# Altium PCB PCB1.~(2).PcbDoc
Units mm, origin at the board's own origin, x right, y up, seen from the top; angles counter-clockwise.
Board outline 70 x 70 mm, 4 copper layers (Top Layer, Internal Plane 1, Internal Plane 2, Bottom Layer), stack 0.462 mm thick; 10 components, 13 nets, 53 pads, 0 vias.
Unrouted connection lines stored in the file: 38.
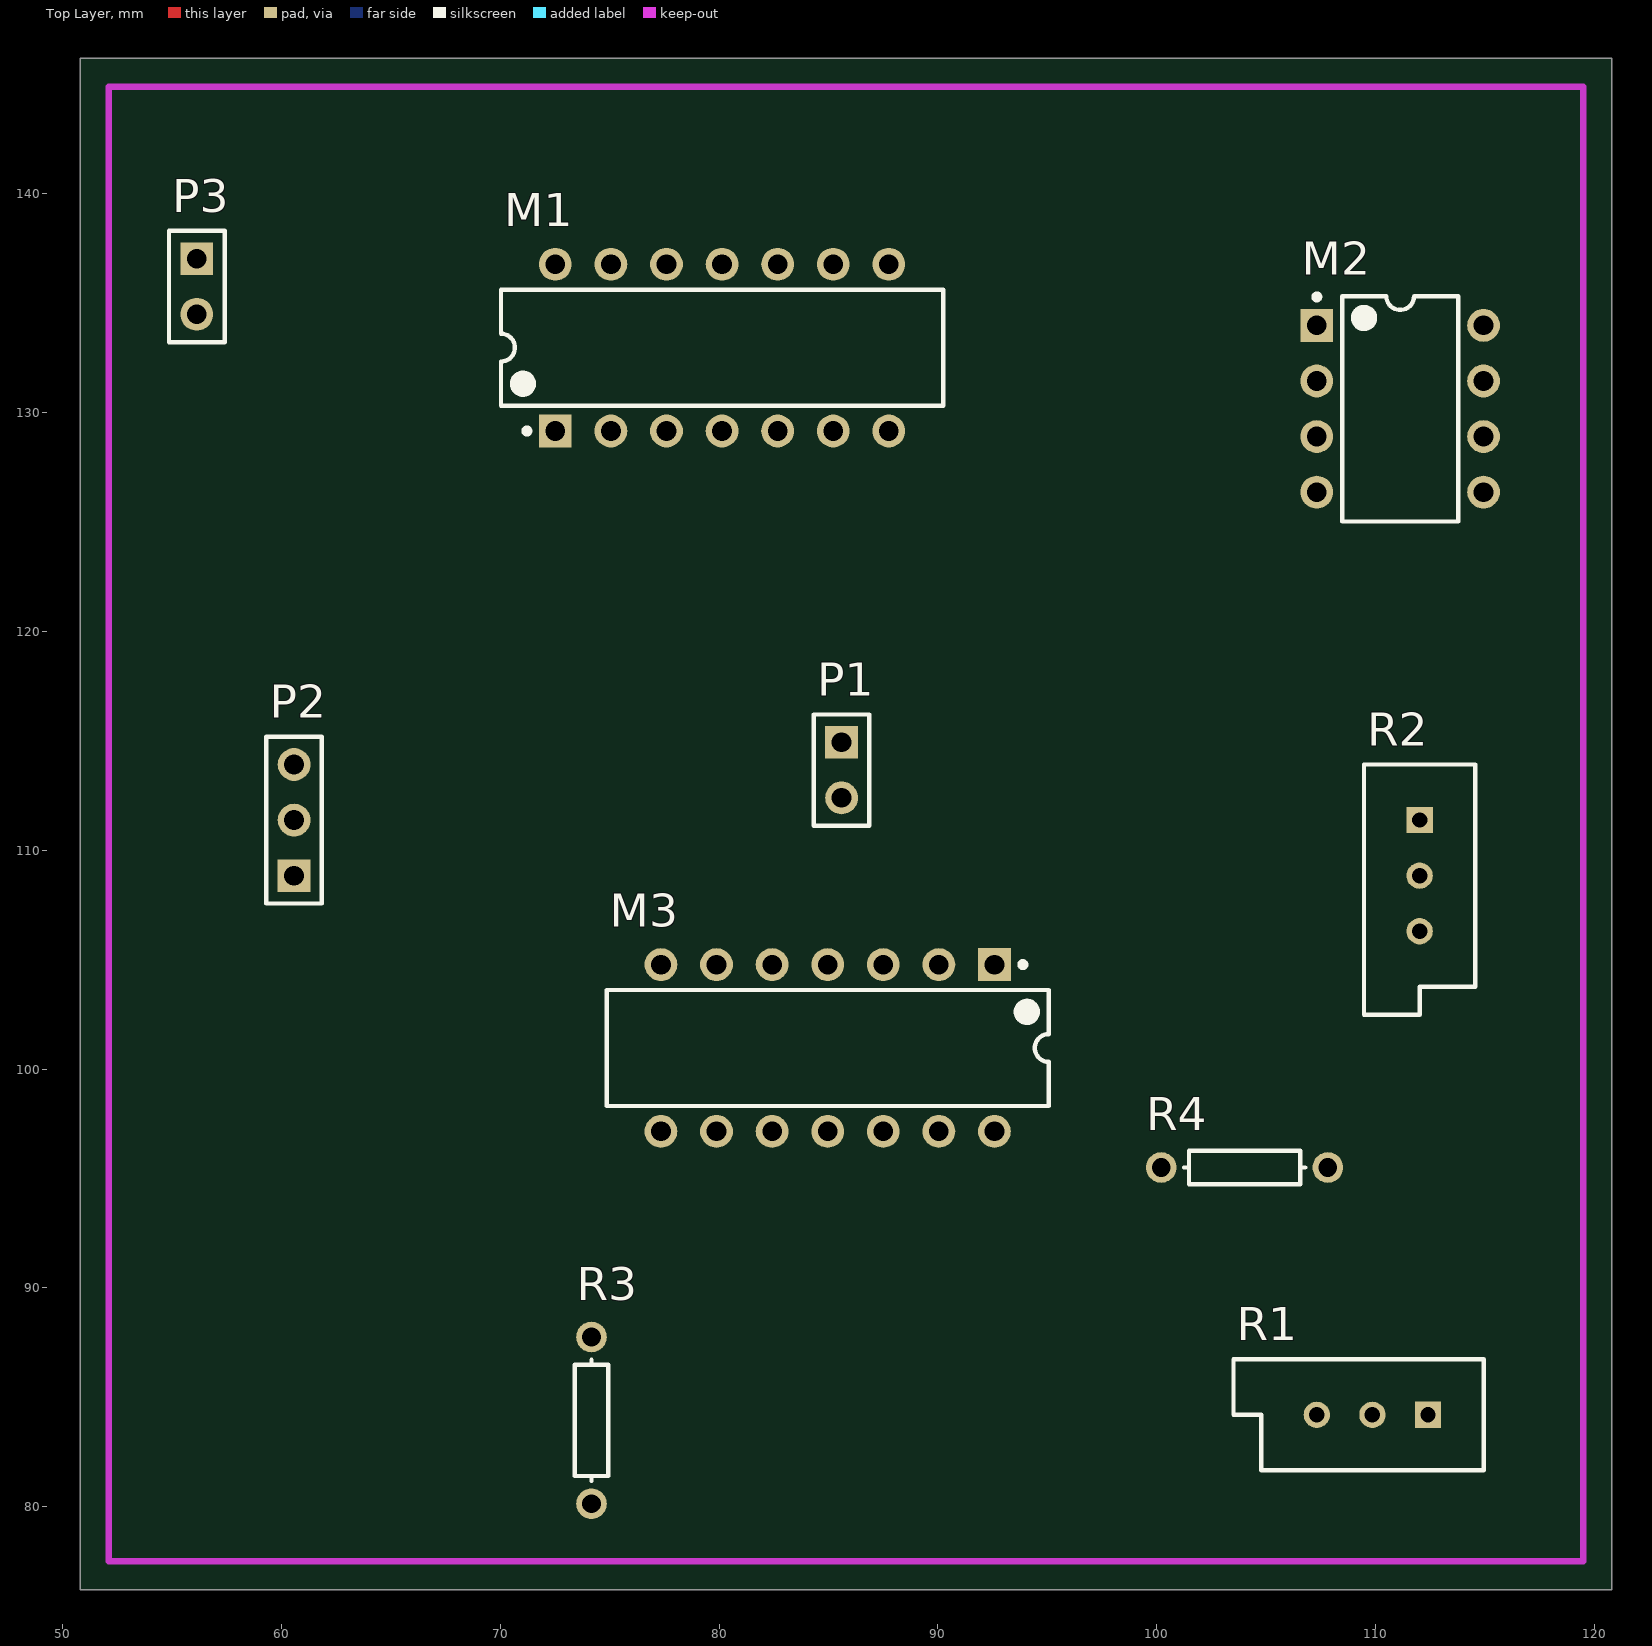
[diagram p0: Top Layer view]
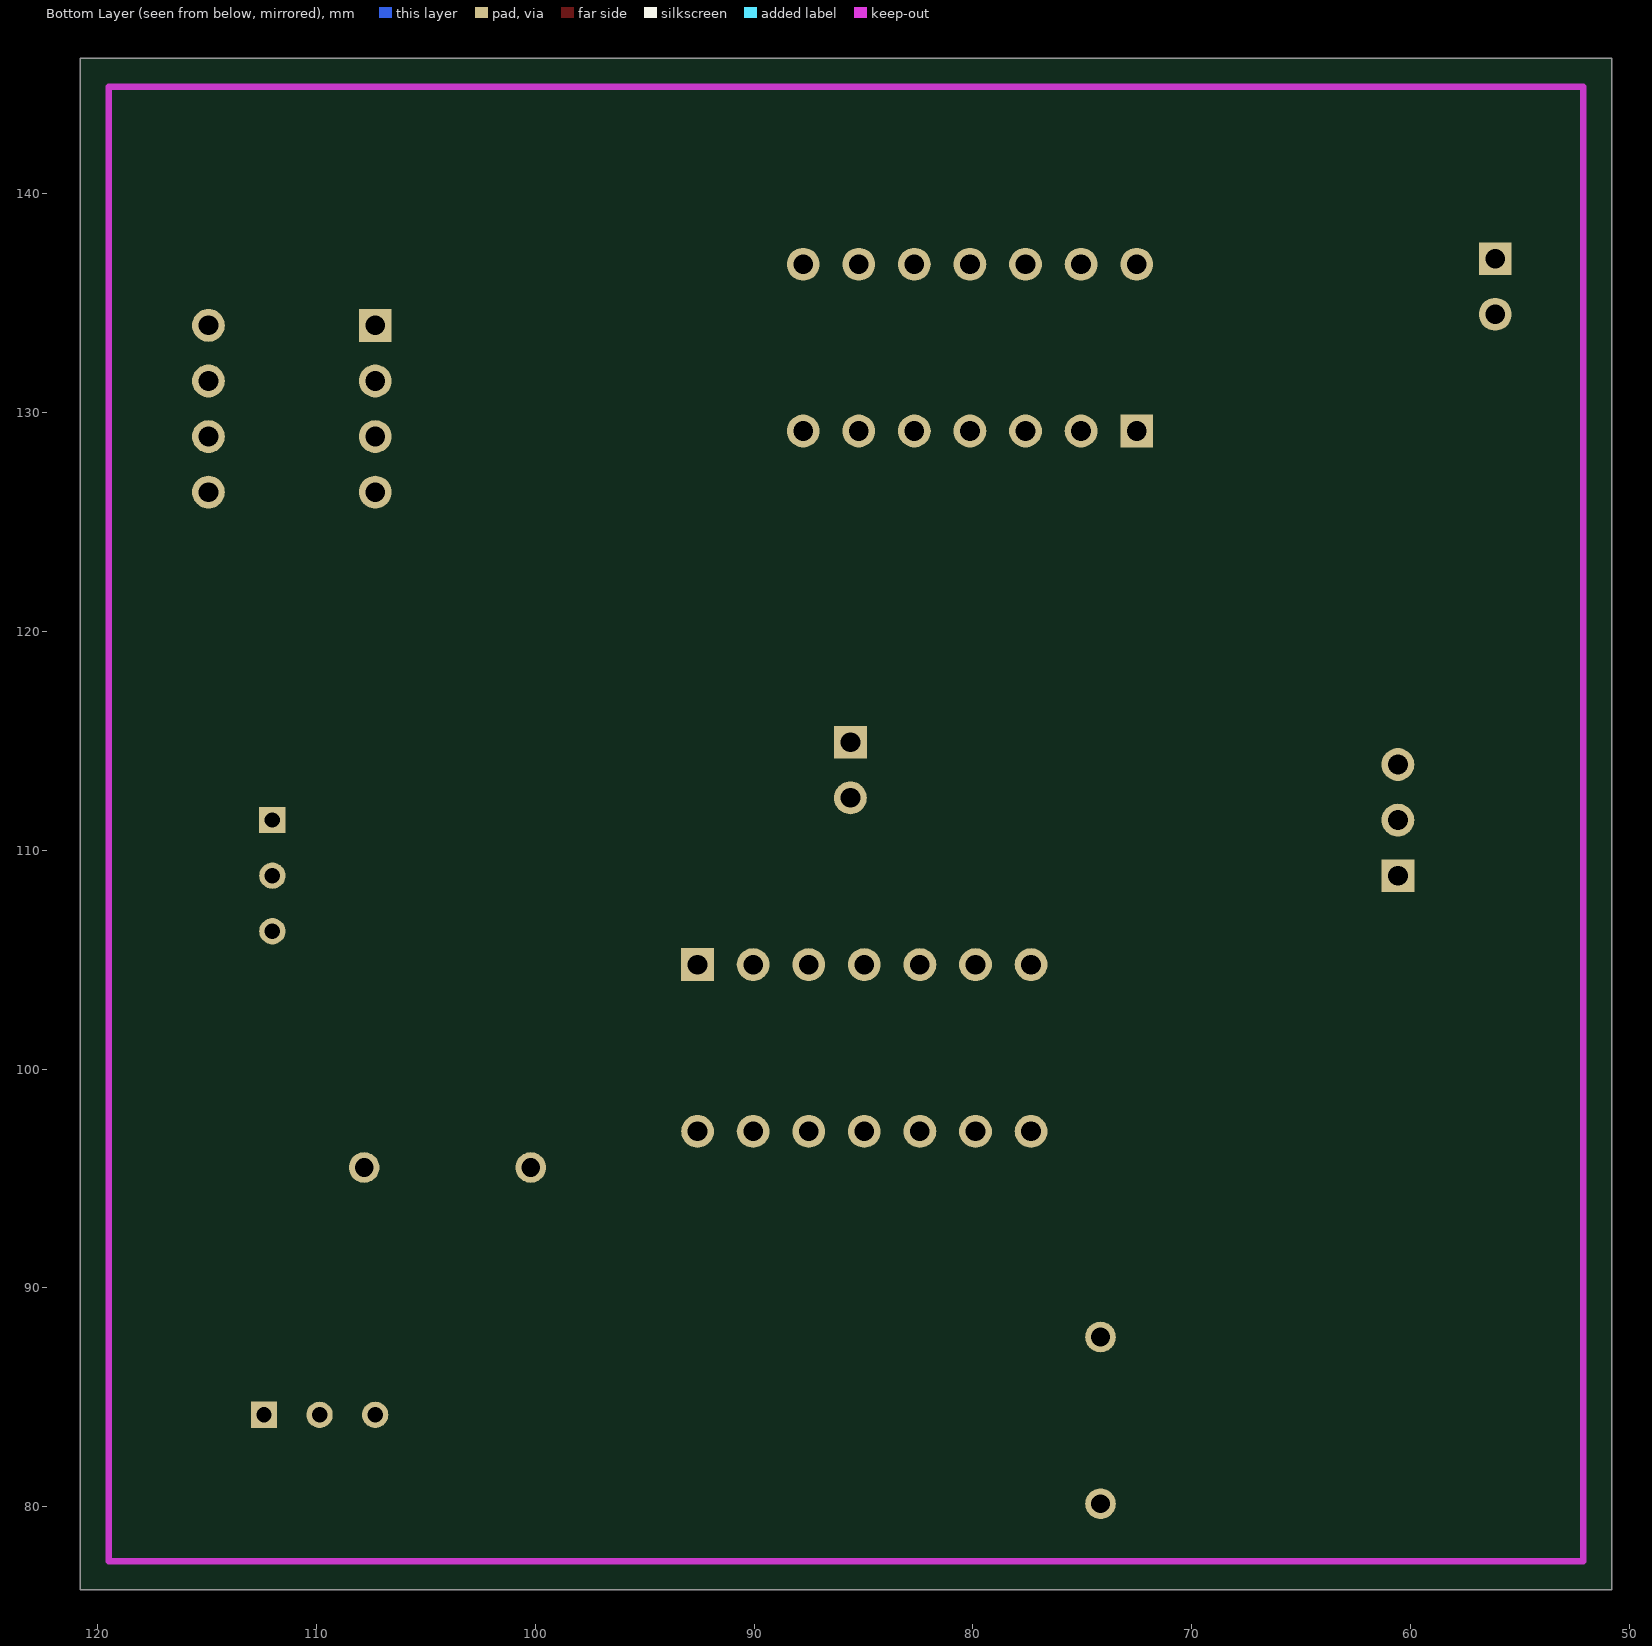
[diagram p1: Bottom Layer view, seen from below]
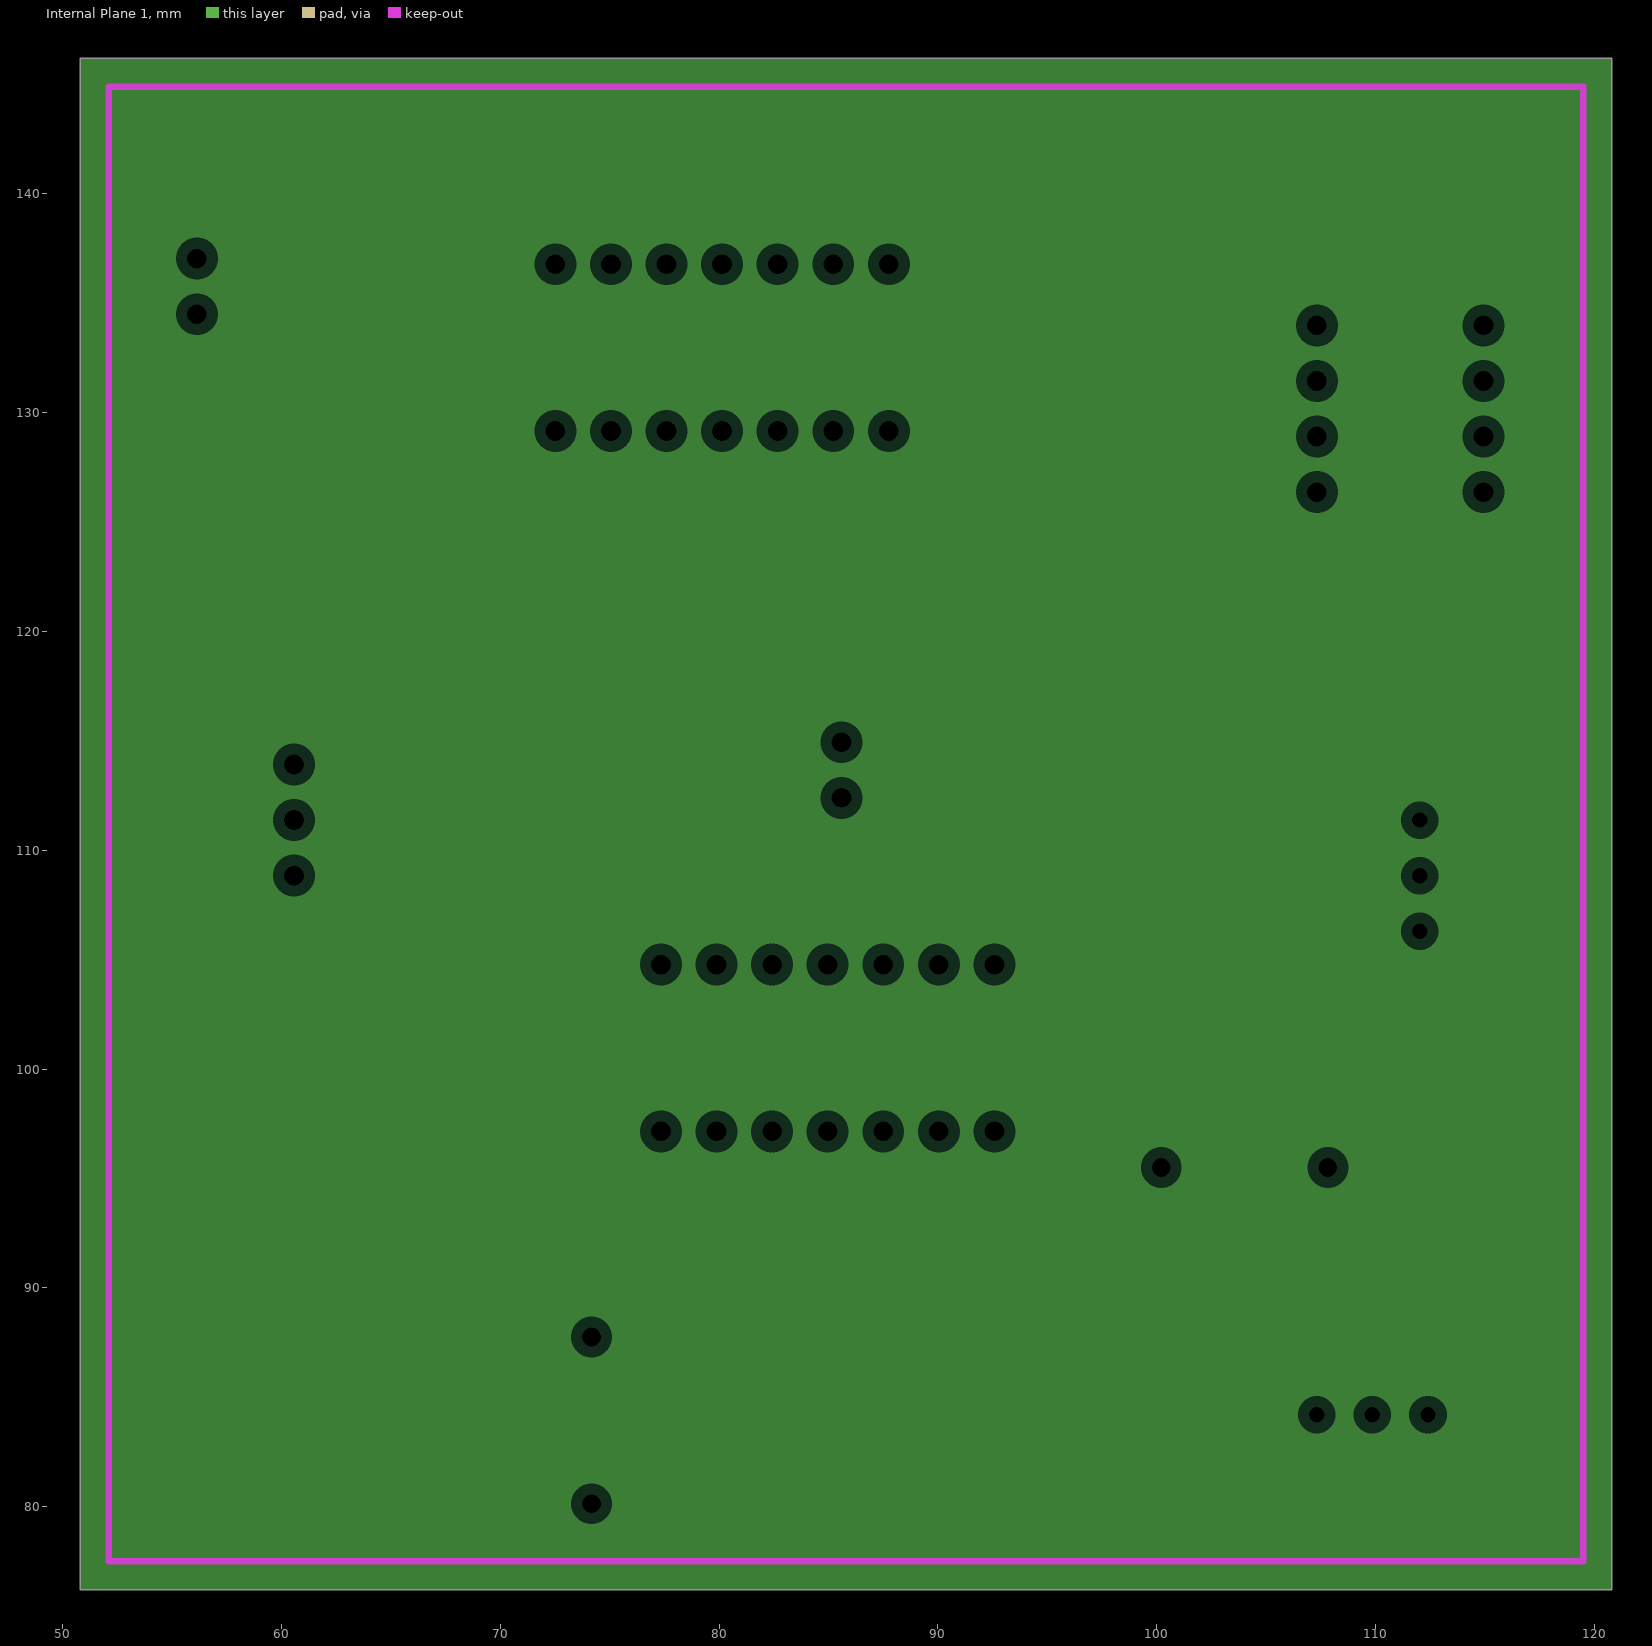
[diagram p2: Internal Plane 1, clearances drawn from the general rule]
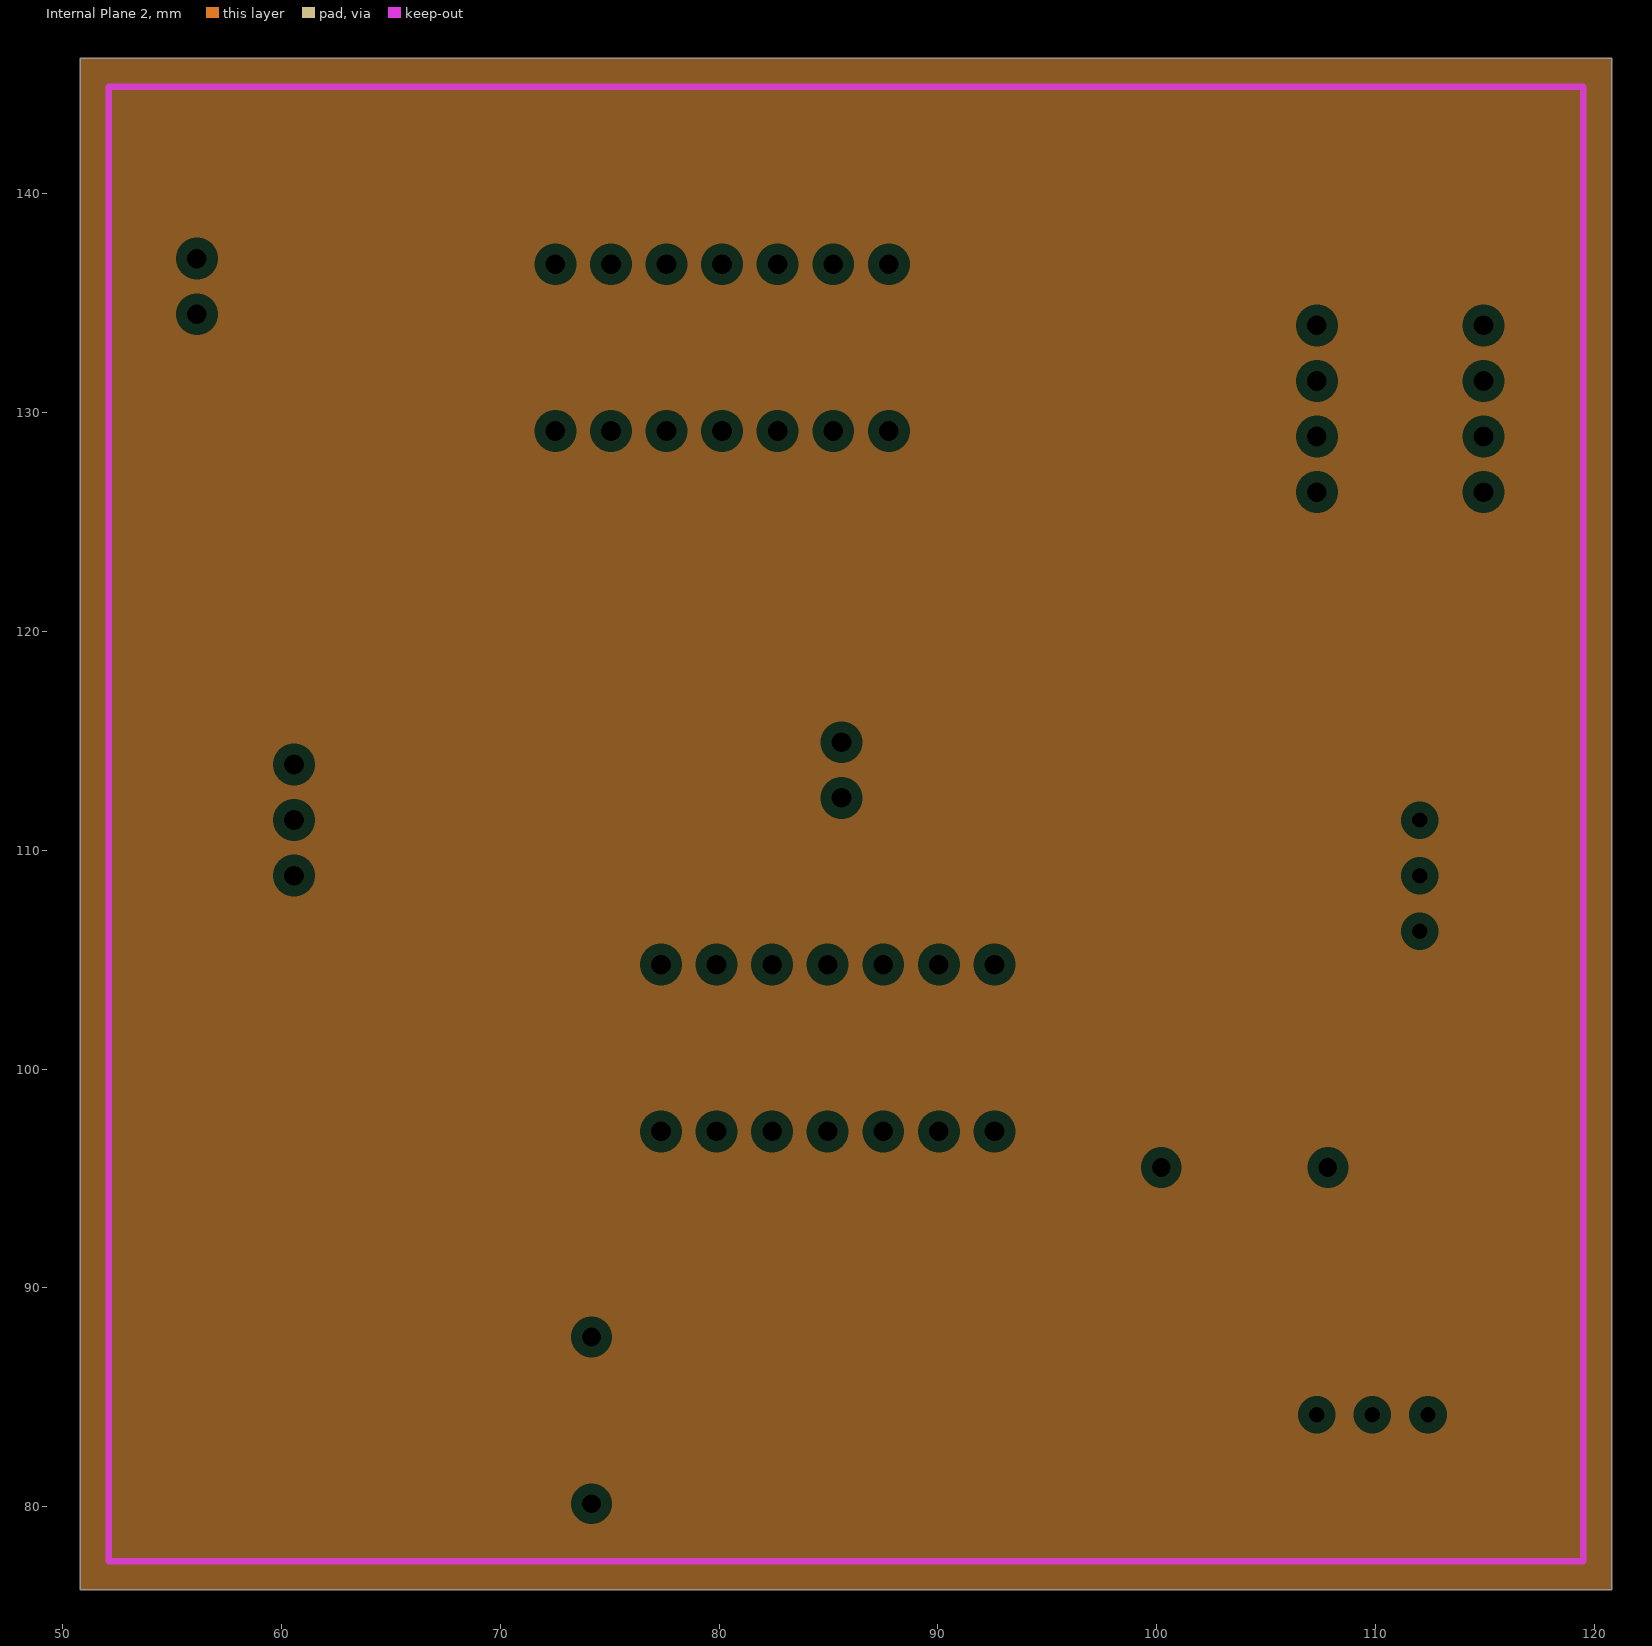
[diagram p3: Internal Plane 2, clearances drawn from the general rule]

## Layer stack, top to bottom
Top Solder: solder mask 0.0102, Solder Resist, Dk 3.5
Top Layer: signal copper 0.0356
Internal Plane 1: plane copper 0.0356
Internal Plane 2: plane copper 0.0356
Dielectric 1: dielectric 0.32, FR-4, Dk 4.8
Bottom Layer: signal copper 0.0356
Bottom Solder: solder mask 0.0102, Solder Resist, Dk 3.5

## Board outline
50.8,76.2 120.8,76.2 120.8,146.2 50.8,146.2

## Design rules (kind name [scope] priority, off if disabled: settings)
Clearance [All] p1: gap=0.8
PlaneClearance [All] p1: clearance=0.508
PlaneConnect [All] p1: planeconnectstyle=Relief reliefexpansion=0.508 reliefentries=4 reliefconductorwidth=0.254 reliefairgap=0.254
PolygonConnect [All] p1: connectstyle=Relief reliefconductorwidth=0.254 reliefentries=4 polygonreliefangle="90 Angle" airgapwidth=0.254
RoutingVias [All] p1: holewidth=0.8 width=1.6 viastyle="Through Hole" minholewidth=0.711 minwidth=1.27 maxholewidth=0.711 maxwidth=1.27
SolderMaskExpansion [All] p1: expansion=0.102
Width [All] p1: maxlimit=0.5 minlimit=0.5 preferedwidth=0.5
28 further rules are at their usual default settings.

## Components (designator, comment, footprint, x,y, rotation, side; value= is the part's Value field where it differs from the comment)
M1 "ALD1105" DIP-14 80.137,132.969 r90 top
M2 "ALD1117" DIP-8 111.125,130.175 r0 top
M3 "ALD1106" DIP-14 84.963,100.965 r270 top
P1 "Header 2" HDR1X2 85.598,114.935 r270 top
P2 "Header 3" HDR1X3 60.579,108.839 r90 top
P3 "Header 2" HDR1X2 56.134,137.033 r270 top
R1 "RPot" VR5 109.855,84.201 r180 top
R2 "RPot" VR5 112.014,108.839 r270 top
R3 "Res1" AXIAL-0.3 74.168,83.947 r90 top
R4 "Res1" AXIAL-0.3 104.013,95.504 r180 top

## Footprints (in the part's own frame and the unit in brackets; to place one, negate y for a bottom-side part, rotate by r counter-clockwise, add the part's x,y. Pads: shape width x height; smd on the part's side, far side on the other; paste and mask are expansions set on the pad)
AXIAL-0.3 [mm] "Axial Device, Thru-Hole; 2 Leads; 0.3 in Pin Spacing"
  round 1.4 hole 0.85: 1(-3.81,0) 2(3.81,0)
  silkscreen extent -2.77,-0.76 2.77,0.76
DIP-8 [mm] "DIP, 8-Pin, Row Spacing 7.62 mm, Pitch 2.54 mm"
  rect 1.5x1.5 hole 0.9: 1(-3.81,3.81)
  round 1.5 hole 0.9: 2(-3.81,1.27) 3(-3.81,-1.27) 4(-3.81,-3.81) 5(3.81,-3.81) 6(3.81,-1.27) 7(3.81,1.27) 8(3.81,3.81)
  silkscreen extent -3.93,-5.15 2.65,5.23, body extent -3.6,-5.15 3.6,5.15, height 5.33
DIP-14 [mm] "DIP, 14-Pin, Row Spacing 7.62 mm, Pitch 2.54 mm"
  rect 1.5x1.5 hole 0.9: 1(-3.81,7.62)
  round 1.5 hole 0.9: 2(-3.81,5.08) 3(-3.81,2.54) 4(-3.81,0) 5(-3.81,-2.54) 6(-3.81,-5.08) 7(-3.81,-7.62) 8(3.81,-7.62) 9(3.81,-5.08) 10(3.81,-2.54) 11(3.81,0) 12(3.81,2.54) 13(3.81,5.08) 14(3.81,7.62)
  silkscreen extent -3.93,-10.1 2.65,10.1, body extent -3.6,-10.1 3.6,10.1, height 5.08
HDR1X2 [mm] "Connector; Header; 2 Position"
  rect 1.5x1.5 hole 0.9: 1(0,0)
  round 1.5 hole 0.9: 2(2.54,0)
  silkscreen extent -1.27,-1.27 3.81,1.27
HDR1X3 [mm] "Connector; Header; 3 Position"
  rect 1.5x1.5 hole 0.9: 1(0,0)
  round 1.5 hole 0.9: 2(2.54,0) 3(5.08,0)
  silkscreen extent -1.27,-1.27 6.35,1.27
VR5 [mm] "Thru-Hole; 3 Leads"
  rect 1.2x1.2 hole 0.7: 1(-2.54,0)
  round 1.2 hole 0.7: 2(0,0) 3(2.54,0)
  silkscreen extent -5.08,-2.54 6.35,2.54

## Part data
M1: "Dual P-channel and dual N-channel matched MOSFET array"
M2: "Dual P-channel matched MOSFET array"
M3: "Quad N-channel matched MOSFET array"
P1 P3: "Header, 2-Pin"
P2: "Header, 3-Pin"
R1 R2: "Potentiometer"
R3 R4: "Resistor"

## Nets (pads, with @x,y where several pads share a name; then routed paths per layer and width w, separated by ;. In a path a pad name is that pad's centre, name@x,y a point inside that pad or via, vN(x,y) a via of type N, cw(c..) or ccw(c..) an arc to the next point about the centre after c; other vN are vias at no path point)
GND: P1.2 P2.3
IN+: M1.13 P3.1
IN-: M1.2 P3.2
NetM1_1: M1.1 M1.5 M1.6 M1.9
NetM1_3: M1.3 M1.4 M1.12 M3.10
NetM1_10: M1.10 M1.14 M2.2
NetM3_1: M3.1 M3.2 M3.6 R3.2
NetM3_9: M3.9 M3.13 M3.14 R4.2
NetR1_2: R1.2 R1.3 R3.1
NetR2_2: R2.2 R2.3 R4.1
OUT2: M2.1 M3.5 P1.1
VDD: M1.7 M1.8 M1.11 M2.3 M2.5 M2.6 M2.7 M2.8 P2.2 R1.1 R2.1
VSS: M3.3 M3.4 M3.7 M3.8 M3.12 P2.1
pads on no net: M2.4 M3.11

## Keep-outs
Keep-Out Layer:
  lines w0.3: 52.1,77.5 52.1,144.9 119.5,144.9 119.5,77.5 52.1,77.5

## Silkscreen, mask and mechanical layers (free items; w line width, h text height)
Drill Drawing:
  text ".LEGEND" at 125.88,81.28 h1.52
  text "Drill Drawing." at 125.88,78.74 h1.52

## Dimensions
52.1,77.5 to 52.1,144.9 on Mechanical 1
52.1,77.5 to 119.5,77.5 on Mechanical 1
